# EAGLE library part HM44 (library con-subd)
SUB-D
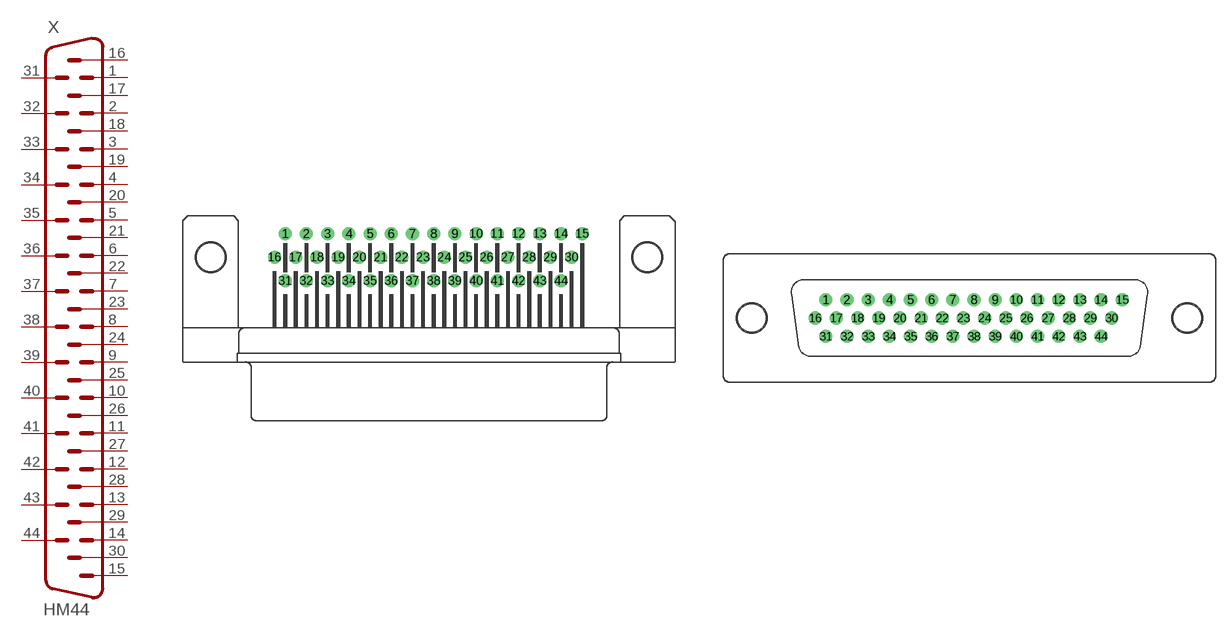
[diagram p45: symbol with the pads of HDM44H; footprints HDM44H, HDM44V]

Designator prefix X

## HM44H (OC_FARNELL: unknown; OC_NEWARK: unknown)  [HDM44H]
1  1  pas
2  2  pas
3  3  pas
4  4  pas
5  5  pas
6  6  pas
7  7  pas
8  8  pas
9  9  pas
10  10  pas
11  11  pas
12  12  pas
13  13  pas
14  14  pas
15  15  pas
16  16  pas
17  17  pas
18  18  pas
19  19  pas
20  20  pas
21  21  pas
22  22  pas
23  23  pas
24  24  pas
25  25  pas
26  26  pas
27  27  pas
28  28  pas
29  29  pas
30  30  pas
31  31  pas
32  32  pas
33  33  pas
34  34  pas
35  35  pas
36  36  pas
37  37  pas
38  38  pas
39  39  pas
40  40  pas
41  41  pas
42  42  pas
43  43  pas
44  44  pas

## HM44V (OC_FARNELL: unknown; OC_NEWARK: unknown)  [HDM44V]
Pads as for HDM44H

## Footprint HDM44H (pad centres in mm)
SUB-D
drill 0.9 round: 1 -15.497,2.54; 2 -13.211,2.54; 3 -10.925,2.54; 4 -8.639,2.54; 5 -6.353,2.54; 6 -4.067,2.54; 7 -1.781,2.54; 8 0.505,2.54; 9 2.791,2.54; 10 5.077,2.54; 11 7.363,2.54; 12 9.649,2.54; 13 11.935,2.54; 14 14.221,2.54; 15 16.507,2.54; 16 -16.64,0; 17 -14.354,0; 18 -12.068,0; 19 -9.782,0; 20 -7.496,0; 21 -5.21,0; 22 -2.924,0; 23 -0.638,0; 24 1.648,0; 25 3.934,0; 26 6.22,0; 27 8.506,0; 28 10.792,0; 29 13.078,0; 30 15.364,0; 31 -15.497,-2.54; 32 -13.211,-2.54; 33 -10.925,-2.54; 34 -8.639,-2.54; 35 -6.353,-2.54; 36 -4.067,-2.54; 37 -1.781,-2.54; 38 0.505,-2.54; 39 2.791,-2.54; 40 5.077,-2.54; 41 7.363,-2.54; 42 9.649,-2.54; 43 11.935,-2.54; 44 14.221,-2.54
hole 3 at -23.52,0
hole 3 at 23.52,0

## Footprint HDM44V (pad centres in mm)
SUB-D
drill 0.9 round: 1 -15.516,1.98; 2 -13.23,1.98; 3 -10.944,1.98; 4 -8.658,1.98; 5 -6.372,1.98; 6 -4.086,1.98; 7 -1.8,1.98; 8 0.486,1.98; 9 2.772,1.98; 10 5.058,1.98; 11 7.344,1.98; 12 9.63,1.98; 13 11.916,1.98; 14 14.202,1.98; 15 16.488,1.98; 16 -16.659,0; 17 -14.373,0; 18 -12.087,0; 19 -9.801,0; 20 -7.515,0; 21 -5.229,0; 22 -2.943,0; 23 -0.657,0; 24 1.629,0; 25 3.915,0; 26 6.201,0; 27 8.487,0; 28 10.773,0; 29 13.059,0; 30 15.345,0; 31 -15.516,-1.98; 32 -13.23,-1.98; 33 -10.944,-1.98; 34 -8.658,-1.98; 35 -6.372,-1.98; 36 -4.086,-1.98; 37 -1.8,-1.98; 38 0.486,-1.98; 39 2.772,-1.98; 40 5.058,-1.98; 41 7.344,-1.98; 42 9.63,-1.98; 43 11.916,-1.98; 44 14.202,-1.98
hole 3 at -23.52,0
hole 3 at 23.52,0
